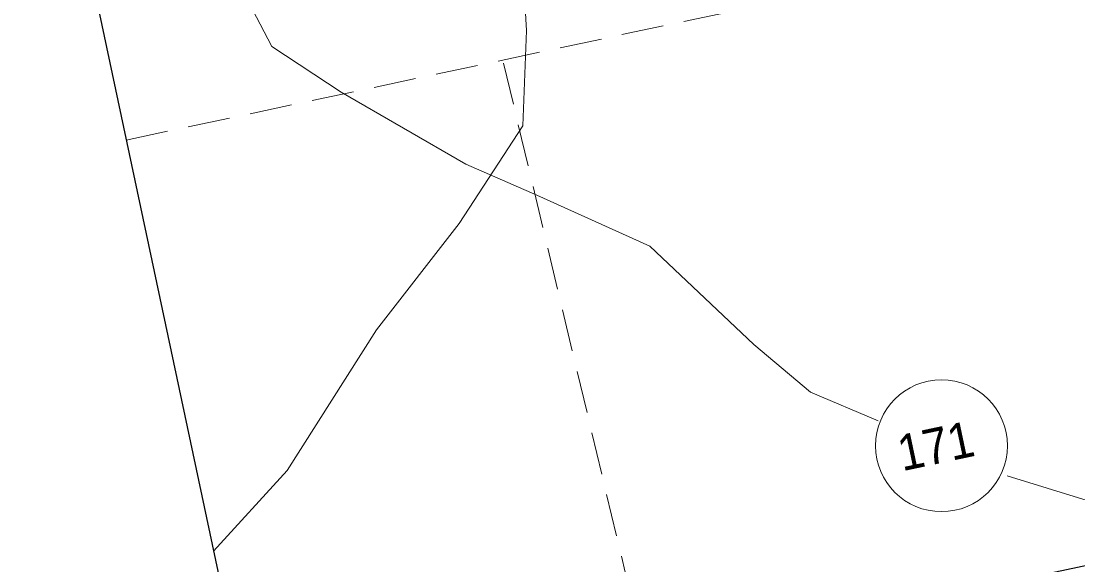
# Model space of a CAD drawing. Extents: x 2357218 to 2371708, y 6973728 to 6980157.
# Drawn here: x 2371235.1 to 2371385.2, y 6977387.6 to 6977464.9 of the extents above; entities that cross this region are included whole.
import ezdxf

# ---------------------------------------------------------------- set-up
doc = ezdxf.new("R2010")
doc.units = 0
doc.header["$LTSCALE"] = 2
doc.linetypes.add('MEDIUM_DASHED', pattern=[4.5, 3, -1.5])
doc.layers.add('62', color=7, linetype='Continuous', lineweight=13)
doc.layers.add('63', color=7, linetype='Continuous', lineweight=13)

msp = doc.modelspace()

# ---------------------------------------------------------------- linework, layer by layer
at = {"layer": '62', "linetype": 'MEDIUM_DASHED'}
for p, q in [((2371250.037, 6977447.964), (2371689.806, 6977541.441)), ((2371323.86, 6977374.259), (2371303.468, 6977459.597))]:
    msp.add_line(p, q, dxfattribs=at)
at = {"layer": '62'}
for p, q in [((2371339.193, 6977418.904), (2371347.249, 6977412.173)), ((2371347.249, 6977412.173), (2371356.856, 6977408.097)), ((2371386.545, 6977396.784), (2371375.178, 6977400.278))]:
    msp.add_line(p, q, dxfattribs=at)
at = {"layer": '62', "lineweight": 25}
msp.add_lwpolyline([(2371171.482, 6977817.538), (2371268.218, 6977362.432), (2371707.985, 6977455.907), (2371611.249, 6977911.015)], dxfattribs=at)
at = {"layer": '62'}
for points in [[(2371237.833, 6977505.388), (2371242.507, 6977501.687), (2371255.93, 6977489.519), (2371264.133, 6977473.872), (2371270.705, 6977461.237), (2371280.549, 6977454.75), (2371298.274, 6977444.527), (2371308.346, 6977440.112), (2371324.438, 6977432.906), (2371339.193, 6977418.904)], [(2371306.134, 6977476.702), (2371306.917, 6977463.506), (2371306.385, 6977449.98), (2371297.351, 6977436.096), (2371285.581, 6977421.013), (2371272.918, 6977401.044), (2371262.444, 6977389.592)]]:
    msp.add_lwpolyline(points, dxfattribs=at)
msp.add_circle((2371365.852, 6977404.547), 9.364, dxfattribs=at)
at = {"layer": '63', "linetype": 'MEDIUM_DASHED'}
for p, q in [((2371250.037, 6977447.964), (2371689.806, 6977541.441)), ((2371323.86, 6977374.259), (2371303.468, 6977459.597))]:
    msp.add_line(p, q, dxfattribs=at)
at = {"layer": '63'}
for p, q in [((2371339.193, 6977418.904), (2371347.249, 6977412.173)), ((2371347.249, 6977412.173), (2371356.856, 6977408.097)), ((2371386.545, 6977396.784), (2371375.178, 6977400.278))]:
    msp.add_line(p, q, dxfattribs=at)
at = {"layer": '63', "lineweight": 25}
msp.add_lwpolyline([(2371171.482, 6977817.538), (2371268.218, 6977362.432), (2371707.985, 6977455.907), (2371611.249, 6977911.015)], dxfattribs=at)
at = {"layer": '63'}
for points in [[(2371237.833, 6977505.388), (2371242.507, 6977501.687), (2371255.93, 6977489.519), (2371264.133, 6977473.872), (2371270.705, 6977461.237), (2371280.549, 6977454.75), (2371298.274, 6977444.527), (2371308.346, 6977440.112), (2371324.438, 6977432.906), (2371339.193, 6977418.904)], [(2371306.134, 6977476.702), (2371306.917, 6977463.506), (2371306.385, 6977449.98), (2371297.351, 6977436.096), (2371285.581, 6977421.013), (2371272.918, 6977401.044), (2371262.444, 6977389.592)]]:
    msp.add_lwpolyline(points, dxfattribs=at)
msp.add_circle((2371365.852, 6977404.547), 9.364, dxfattribs=at)

# ---------------------------------------------------------------- texts
at = {"layer": '62', "width": 0.95}
msp.add_text('171', height=5.099, rotation=12, dxfattribs=at).set_placement((2371360.271, 6977400.911))
at = {"layer": '63', "width": 0.95}
msp.add_text('171', height=5.099, rotation=12, dxfattribs=at).set_placement((2371360.271, 6977400.911))

doc.saveas('drawing.dxf')
